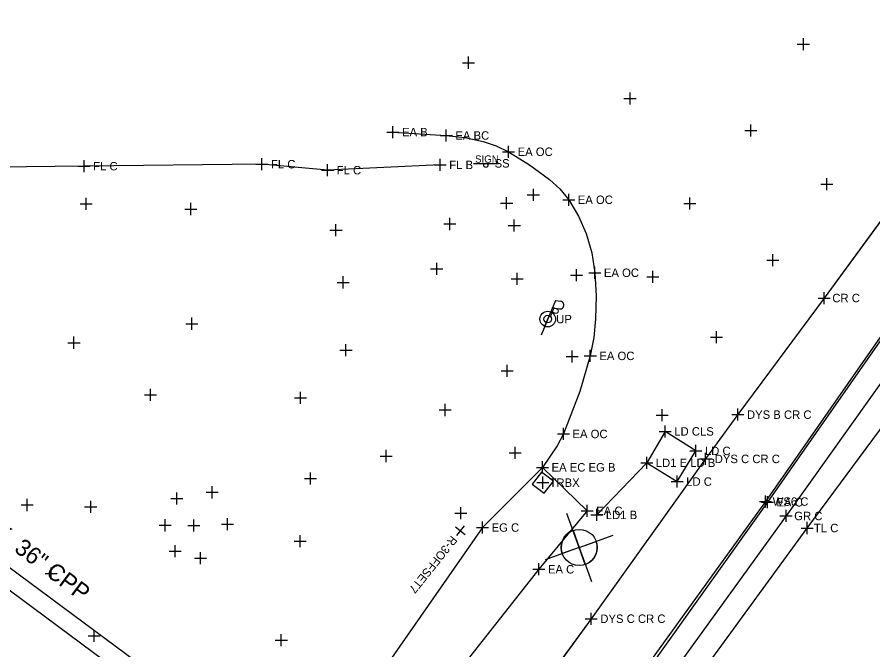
# Model space of a CAD drawing. Extents: x 1324236 to 1326110, y 459090 to 460782.
# Drawn here: x 1325315.8 to 1325457.8, y 460421.8 to 460526.7 of the extents above; entities that cross this region are included whole.
import ezdxf

# ---------------------------------------------------------------- set-up
doc = ezdxf.new("R2010")
doc.units = 0
for name, color, linetype in [('BD_X_Canopy', 7, 'Continuous'), ('DR_X_Ditch', 7, 'Continuous'), ('DT_X_Contour_Minor', 7, 'Continuous'), ('DT_X_Island', 7, 'Continuous'), ('DV_X_Property_Line', 7, 'Continuous'), ('GT_Project_Soil_Boring', 7, 'Continuous'), ('LT_X_Poles', 7, 'Continuous'), ('PM_X_CL_Double_Solid', 7, 'Continuous'), ('PM_X_Edge_Line', 7, 'Continuous'), ('PM_X_Parking_Lot_Stall', 7, 'Continuous'), ('PV_X_Shoulder', 7, 'Continuous'), ('RD_X_Concrete_Barrier', 7, 'Continuous'), ('RD_X_GR_Lt', 7, 'Continuous'), ('RW_X_CL', 7, 'Continuous'), ('RW_X_Esmt_SH', 7, 'Continuous'), ('RW_X_Fee_RW', 7, 'Continuous'), ('SC_Scratch1', 7, 'Continuous'), ('UT_X_Telecom', 7, 'Continuous'), ('VG_X_Flower_Bed', 7, 'Continuous')]:
    doc.layers.add(name, color=color, linetype=linetype)

msp = doc.modelspace()

# ---------------------------------------------------------------- linework, layer by layer
at = {"layer": 'BD_X_Canopy'}
msp.add_lwpolyline([(1325487.31, 460531.49), (1325482.01, 460524.62), (1325468.2, 460505.38), (1325449.72, 460480.14), (1325435.41, 460460.81), (1325430.06, 460453.47), (1325411.08, 460426.97), (1325392.29, 460401.31), (1325374.47, 460377.45), (1325359.08, 460355.34), (1325347.31, 460339.76), (1325334.63, 460323.86), (1325318.91, 460302.58), (1325303.42, 460281.57), (1325299.27, 460276.07), (1325289.28, 460262.48), (1325282.05, 460252.54), (1325264.96, 460229.27), (1325246.47, 460204.3), (1325228.59, 460180.03), (1325210.75, 460156.01)], dxfattribs=at)
at = {"layer": 'DR_X_Ditch'}
for points in [[(1325378.18, 460507.65), (1325387.03, 460507.09), (1325390.1, 460506.74), (1325393.12, 460506.1), (1325395.3, 460505.38), (1325397.36, 460504.39), (1325400.84, 460502.24), (1325404.13, 460499.82), (1325405.85, 460498.24), (1325407.34, 460496.43), (1325408.98, 460493.74), (1325410.25, 460490.84), (1325411.17, 460487.63), (1325411.67, 460484.33), (1325411.87, 460480.51), (1325411.8, 460476.68), (1325411.49, 460473.59), (1325410.92, 460470.55), (1325409.2, 460464.63), (1325406.46, 460457.61), (1325405.43, 460455.66), (1325402.99, 460452.07), (1325410.4, 460444.86), (1325402.39, 460435.17), (1325382.22, 460409.68)], [(1325459.02, 460473.66), (1325440.01, 460446.4), (1325420.89, 460420.01)]]:
    msp.add_lwpolyline(points, dxfattribs=at)
at = {"layer": 'DT_X_Contour_Minor'}
msp.add_line((1325391.53, 460502.47), (1325395.66, 460502.47), dxfattribs=at)
msp.add_circle((1325393.59, 460502.13), 0.344, dxfattribs=at)
at = {"layer": 'DT_X_Island'}
for p, q in [((1325468.2, 460505.38), (1325449.72, 460480.14)), ((1325449.72, 460480.14), (1325435.41, 460460.81)), ((1325435.41, 460460.81), (1325430.06, 460453.47)), ((1325430.06, 460453.47), (1325411.08, 460426.97)), ((1325411.08, 460426.97), (1325392.29, 460401.31))]:
    msp.add_line(p, q, dxfattribs=at)
at = {"layer": 'DV_X_Property_Line'}
for p, q in [((1325377.18, 460507.65), (1325379.18, 460507.65)), ((1325378.18, 460506.65), (1325378.18, 460508.65)), ((1325387.03, 460506.09), (1325387.03, 460508.09)), ((1325386.03, 460507.09), (1325388.03, 460507.09)), ((1325397.36, 460503.39), (1325397.36, 460505.39)), ((1325396.36, 460504.39), (1325398.36, 460504.39)), ((1325406.34, 460496.43), (1325408.34, 460496.43)), ((1325407.34, 460495.43), (1325407.34, 460497.43)), ((1325411.67, 460483.33), (1325411.67, 460485.33)), ((1325410.67, 460484.33), (1325412.67, 460484.33)), ((1325410.92, 460469.55), (1325410.92, 460471.55)), ((1325409.92, 460470.55), (1325411.92, 460470.55)), ((1325406.46, 460456.61), (1325406.46, 460458.61)), ((1325405.46, 460457.61), (1325407.46, 460457.61)), ((1325402.99, 460451.07), (1325402.99, 460453.07)), ((1325401.99, 460452.07), (1325403.99, 460452.07)), ((1325440.31, 460445.28), (1325440.31, 460447.28)), ((1325410.4, 460443.86), (1325410.4, 460445.86)), ((1325439.31, 460446.28), (1325441.31, 460446.28)), ((1325409.4, 460444.86), (1325411.4, 460444.86)), ((1325393.04, 460441.09), (1325393.04, 460443.09)), ((1325392.04, 460442.09), (1325394.04, 460442.09)), ((1325402.39, 460434.17), (1325402.39, 460436.17)), ((1325401.39, 460435.17), (1325403.39, 460435.17))]:
    msp.add_line(p, q, dxfattribs=at)
at = {"layer": 'GT_Project_Soil_Boring'}
for p, q in [((1325409.08, 460438.79), (1325407.05, 460444.43)), ((1325408.06, 460441.61), (1325409.08, 460438.79)), ((1325409.08, 460438.79), (1325414.72, 460440.81)), ((1325409.08, 460438.79), (1325411.9, 460439.8)), ((1325409.08, 460438.79), (1325403.43, 460436.76)), ((1325409.08, 460438.79), (1325406.25, 460437.77)), ((1325409.08, 460438.79), (1325411.1, 460433.14)), ((1325410.09, 460435.96), (1325409.08, 460438.79))]:
    msp.add_line(p, q, dxfattribs=at)
msp.add_circle((1325409.08, 460438.79), 3, dxfattribs=at)
for start, end in [(109.7344, 199.7344), (289.7344, 19.7344)]:
    msp.add_arc((1325409.08, 460438.79), 3, start, end, dxfattribs=at)
at = {"layer": 'LT_X_Poles'}
for points in [[(1325459.02, 460473.66), (1325440.01, 460446.4), (1325420.89, 460420.01)], [(1325435.41, 460460.81), (1325430.06, 460453.47), (1325411.08, 460426.97), (1325392.29, 460401.31), (1325374.47, 460377.45)]]:
    msp.add_lwpolyline(points, dxfattribs=at)
at = {"layer": 'PM_X_CL_Double_Solid'}
for p, q in [((1325326.93, 460502), (1325296.77, 460501.69)), ((1325356.44, 460502.33), (1325326.93, 460502)), ((1325367.34, 460501.34), (1325356.44, 460502.33)), ((1325386.01, 460502.22), (1325367.34, 460501.34)), ((1325435.41, 460460.81), (1325430.06, 460453.47)), ((1325430.06, 460453.47), (1325411.08, 460426.97)), ((1325411.08, 460426.97), (1325392.29, 460401.31))]:
    msp.add_line(p, q, dxfattribs=at)
at = {"layer": 'PM_X_Edge_Line'}
for p, q in [((1325459.02, 460473.66), (1325440.01, 460446.4)), ((1325440.01, 460446.4), (1325420.89, 460420.01))]:
    msp.add_line(p, q, dxfattribs=at)
at = {"layer": 'PM_X_Parking_Lot_Stall'}
for p, q in [((1325462.87, 460471.32), (1325443.39, 460444.01)), ((1325443.39, 460444.01), (1325424.35, 460417.69))]:
    msp.add_line(p, q, dxfattribs=at)
at = {"layer": 'PV_X_Shoulder'}
for points in [[(1325459.28, 460473.45), (1325440.31, 460446.28), (1325421.28, 460419.66)], [(1325402.99, 460452.07), (1325393.04, 460442.09), (1325373.73, 460414.41), (1325365.88, 460405.04), (1325350.78, 460385.39)]]:
    msp.add_lwpolyline(points, dxfattribs=at)
at = {"layer": 'RD_X_Concrete_Barrier'}
for p, q in [((1325405.13, 460479.72), (1325402.76, 460473.97)), ((1325405.13, 460479.72), (1325405.97, 460479.61)), ((1325404.62, 460478.5), (1325405.8, 460478.34))]:
    msp.add_line(p, q, dxfattribs=at)
msp.add_lwpolyline([(1325403.27, 460447.78), (1325404.79, 460449.76), (1325402.81, 460451.28), (1325401.29, 460449.3)], close=True, dxfattribs=at)
msp.add_circle((1325403.86, 460476.65), 1.3, dxfattribs=at)
msp.add_arc((1325405.9, 460478.97), 0.638, 261.5023, 83.7489, dxfattribs=at)
at = {"layer": 'RD_X_GR_Lt'}
for p, q in [((1325446.9, 460442.01), (1325466.37, 460468.29)), ((1325427.28, 460415.17), (1325446.9, 460442.01))]:
    msp.add_line(p, q, dxfattribs=at)
at = {"layer": 'RW_X_CL'}
for p, q in [((1325445.27, 460522.23), (1325447.27, 460522.23)), ((1325446.27, 460521.23), (1325446.27, 460523.23)), ((1325389.69, 460519.16), (1325391.69, 460519.16)), ((1325390.69, 460518.16), (1325390.69, 460520.16)), ((1325417.51, 460512.23), (1325417.51, 460514.23)), ((1325416.51, 460513.23), (1325418.51, 460513.23)), ((1325436.56, 460507.91), (1325438.56, 460507.91)), ((1325437.56, 460506.91), (1325437.56, 460508.91)), ((1325450.18, 460498.03), (1325450.18, 460500.03)), ((1325401.47, 460496.23), (1325401.47, 460498.23)), ((1325449.18, 460499.03), (1325451.18, 460499.03)), ((1325327.28, 460494.74), (1325327.28, 460496.74)), ((1325397.04, 460494.89), (1325397.04, 460496.89)), ((1325400.47, 460497.23), (1325402.47, 460497.23)), ((1325427.45, 460494.81), (1325427.45, 460496.81)), ((1325326.28, 460495.74), (1325328.28, 460495.74)), ((1325343.62, 460494.9), (1325345.62, 460494.9)), ((1325344.62, 460493.9), (1325344.62, 460495.9)), ((1325396.04, 460495.89), (1325398.04, 460495.89)), ((1325426.45, 460495.81), (1325428.45, 460495.81)), ((1325368.72, 460490.38), (1325368.72, 460492.38)), ((1325386.63, 460492.42), (1325388.63, 460492.42)), ((1325387.63, 460491.42), (1325387.63, 460493.42)), ((1325397.31, 460492.16), (1325399.31, 460492.16)), ((1325398.31, 460491.16), (1325398.31, 460493.16)), ((1325367.72, 460491.38), (1325369.72, 460491.38)), ((1325440.2, 460486.41), (1325442.2, 460486.41)), ((1325441.2, 460485.41), (1325441.2, 460487.41)), ((1325384.43, 460484.98), (1325386.43, 460484.98)), ((1325385.43, 460483.98), (1325385.43, 460485.98)), ((1325369.92, 460481.74), (1325369.92, 460483.74)), ((1325398.78, 460482.33), (1325398.78, 460484.33)), ((1325407.61, 460483.91), (1325409.61, 460483.91)), ((1325408.61, 460482.91), (1325408.61, 460484.91)), ((1325420.3, 460483.64), (1325422.3, 460483.64)), ((1325421.3, 460482.64), (1325421.3, 460484.64)), ((1325368.92, 460482.74), (1325370.92, 460482.74)), ((1325397.78, 460483.33), (1325399.78, 460483.33)), ((1325449.72, 460479.14), (1325449.72, 460481.14)), ((1325448.72, 460480.14), (1325450.72, 460480.14)), ((1325344.78, 460474.89), (1325344.78, 460476.89)), ((1325343.78, 460475.89), (1325345.78, 460475.89)), ((1325325.25, 460471.74), (1325325.25, 460473.74)), ((1325430.87, 460473.67), (1325432.87, 460473.67)), ((1325431.87, 460472.67), (1325431.87, 460474.67)), ((1325324.25, 460472.74), (1325326.25, 460472.74)), ((1325370.38, 460470.49), (1325370.38, 460472.49)), ((1325369.38, 460471.49), (1325371.38, 460471.49)), ((1325407.91, 460469.44), (1325407.91, 460471.44)), ((1325406.91, 460470.44), (1325408.91, 460470.44)), ((1325396.11, 460468.06), (1325398.11, 460468.06)), ((1325397.11, 460467.06), (1325397.11, 460469.06)), ((1325337.93, 460463.09), (1325337.93, 460465.09)), ((1325336.93, 460464.09), (1325338.93, 460464.09)), ((1325362.85, 460462.61), (1325362.85, 460464.61)), ((1325361.85, 460463.61), (1325363.85, 460463.61)), ((1325386.85, 460460.58), (1325386.85, 460462.58)), ((1325385.85, 460461.58), (1325387.85, 460461.58)), ((1325422.84, 460459.7), (1325422.84, 460461.7)), ((1325434.41, 460460.81), (1325436.41, 460460.81)), ((1325435.41, 460459.81), (1325435.41, 460461.81)), ((1325421.84, 460460.7), (1325423.84, 460460.7)), ((1325398.44, 460453.49), (1325398.44, 460455.49)), ((1325376.07, 460453.95), (1325378.07, 460453.95)), ((1325377.07, 460452.95), (1325377.07, 460454.95)), ((1325397.44, 460454.49), (1325399.44, 460454.49)), ((1325420.28, 460451.82), (1325420.28, 460453.82)), ((1325430.06, 460452.47), (1325430.06, 460454.47)), ((1325419.28, 460452.82), (1325421.28, 460452.82)), ((1325429.06, 460453.47), (1325431.06, 460453.47)), ((1325364.47, 460449.22), (1325364.47, 460451.22)), ((1325363.47, 460450.22), (1325365.47, 460450.22)), ((1325402.04, 460449.53), (1325404.04, 460449.53)), ((1325403.04, 460448.53), (1325403.04, 460450.53)), ((1325348.19, 460446.93), (1325348.19, 460448.93)), ((1325317.49, 460444.83), (1325317.49, 460446.83)), ((1325341.32, 460446.91), (1325343.32, 460446.91)), ((1325342.32, 460445.91), (1325342.32, 460447.91)), ((1325347.19, 460447.93), (1325349.19, 460447.93)), ((1325440.01, 460445.4), (1325440.01, 460447.4)), ((1325316.49, 460445.83), (1325318.49, 460445.83)), ((1325327.02, 460445.52), (1325329.02, 460445.52)), ((1325328.02, 460444.52), (1325328.02, 460446.52)), ((1325389.42, 460443.49), (1325389.42, 460445.49)), ((1325412, 460443.18), (1325412, 460445.18)), ((1325439.01, 460446.4), (1325441.01, 460446.4)), ((1325388.42, 460444.49), (1325390.42, 460444.49)), ((1325411, 460444.18), (1325413, 460444.18)), ((1325339.36, 460442.46), (1325341.36, 460442.46)), ((1325340.36, 460441.46), (1325340.36, 460443.46)), ((1325344.15, 460442.41), (1325346.15, 460442.41)), ((1325345.15, 460441.41), (1325345.15, 460443.41)), ((1325349.73, 460442.66), (1325351.73, 460442.66)), ((1325350.73, 460441.66), (1325350.73, 460443.66)), ((1325389.97, 460442.36), (1325388.73, 460440.79)), ((1325388.57, 460442.2), (1325390.13, 460440.95)), ((1325361.76, 460439.85), (1325363.76, 460439.85)), ((1325362.76, 460438.85), (1325362.76, 460440.85)), ((1325341.04, 460438.17), (1325343.04, 460438.17)), ((1325342.04, 460437.17), (1325342.04, 460439.17)), ((1325345.24, 460437.01), (1325347.24, 460437.01)), ((1325346.24, 460436.01), (1325346.24, 460438.01)), ((1325321.47, 460433.46), (1325321.47, 460435.46)), ((1325320.47, 460434.46), (1325322.47, 460434.46)), ((1325410.08, 460426.97), (1325412.08, 460426.97)), ((1325411.08, 460425.97), (1325411.08, 460427.97)), ((1325327.6, 460424.13), (1325329.6, 460424.13)), ((1325328.6, 460423.13), (1325328.6, 460425.13)), ((1325359.65, 460422.41), (1325359.65, 460424.41)), ((1325358.65, 460423.41), (1325360.65, 460423.41))]:
    msp.add_line(p, q, dxfattribs=at)
at = {"layer": 'RW_X_Esmt_SH'}
for p, q in [((1325325.93, 460502), (1325327.93, 460502)), ((1325326.93, 460501), (1325326.93, 460503)), ((1325355.44, 460502.33), (1325357.44, 460502.33)), ((1325356.44, 460501.33), (1325356.44, 460503.33)), ((1325367.34, 460500.34), (1325367.34, 460502.34)), ((1325385.01, 460502.22), (1325387.01, 460502.22)), ((1325386.01, 460501.22), (1325386.01, 460503.22)), ((1325366.34, 460501.34), (1325368.34, 460501.34)), ((1325422.35, 460458.03), (1325424.35, 460458.03)), ((1325423.35, 460457.03), (1325423.35, 460459.03)), ((1325428.44, 460453.8), (1325428.44, 460455.8)), ((1325427.44, 460454.8), (1325429.44, 460454.8)), ((1325424.33, 460449.71), (1325426.33, 460449.71)), ((1325425.33, 460448.71), (1325425.33, 460450.71)), ((1325442.39, 460444.01), (1325444.39, 460444.01)), ((1325443.39, 460443.01), (1325443.39, 460445.01)), ((1325446.9, 460441.01), (1325446.9, 460443.01)), ((1325445.9, 460442.01), (1325447.9, 460442.01))]:
    msp.add_line(p, q, dxfattribs=at)
at = {"layer": 'RW_X_Fee_RW'}
for p, q in [((1325423.35, 460458.03), (1325420.28, 460452.82)), ((1325428.44, 460454.8), (1325423.35, 460458.03)), ((1325425.33, 460449.71), (1325428.44, 460454.8)), ((1325412, 460444.18), (1325420.28, 460452.82)), ((1325420.28, 460452.82), (1325425.33, 460449.71))]:
    msp.add_line(p, q, dxfattribs=at)
at = {"layer": 'SC_Scratch1'}
msp.add_line((1325403.33, 460475.36), (1325404.13, 460477.31), dxfattribs=at)
msp.add_circle((1325403.86, 460476.65), 0.63, dxfattribs=at)
at = {"layer": 'VG_X_Flower_Bed'}
for p, q in [((1325304.91, 460442.59), (1325427.5, 460351.85)), ((1325303.12, 460440.18), (1325425.72, 460349.44))]:
    msp.add_line(p, q, dxfattribs=at)

# ---------------------------------------------------------------- texts
at = {"layer": 'DT_X_Contour_Minor'}
for s, height, p in [('SIGN', 1.205, (1325391.8, 460502.58)), ('SS', 1.4, (1325395.04, 460501.77))]:
    msp.add_text(s, height=height, dxfattribs=at).set_placement(p)
at = {"layer": 'DV_X_Property_Line'}
for s, p in [('EA B', (1325379.68, 460506.95)), ('EA BC', (1325388.53, 460506.39)), ('EA OC', (1325398.86, 460503.69)), ('EA OC', (1325408.84, 460495.73)), ('EA OC', (1325413.17, 460483.63)), ('EA OC', (1325412.42, 460469.85)), ('EA OC', (1325407.96, 460456.91)), ('EA EC EG B', (1325404.49, 460451.37)), ('EA C', (1325441.81, 460445.58)), ('EA C', (1325411.9, 460444.16)), ('EG C', (1325394.54, 460441.39)), ('EA C', (1325403.89, 460434.47))]:
    msp.add_text(s, height=1.4, dxfattribs=at).set_placement(p)
at = {"layer": 'RW_X_CL'}
for s, p in [('CR C', (1325451.08, 460479.44)), ('DYS B CR C', (1325436.91, 460460.11)), ('DYS C CR C', (1325431.56, 460452.77)), ('LD1 E LD B', (1325421.78, 460452.12)), ('TRBX', (1325404.16, 460448.83)), ('WS6 C', (1325441.18, 460445.7)), ('LD1 B', (1325413.5, 460443.48)), ('DYS C CR C', (1325412.58, 460426.27))]:
    msp.add_text(s, height=1.4, dxfattribs=at).set_placement(p)
msp.add_text('R-3OFFSET7', height=1.4, rotation=231.3852, dxfattribs=at).set_placement((1325387.87, 460440.84))
at = {"layer": 'RW_X_Esmt_SH'}
for s, p in [('FL C', (1325328.43, 460501.3)), ('FL C', (1325357.94, 460501.63)), ('FL C', (1325368.84, 460500.64)), ('FL B', (1325387.51, 460501.52)), ('LD CLS', (1325424.85, 460457.33)), ('LD C', (1325429.94, 460454.1)), ('LD C', (1325426.83, 460449.01)), ('GR C', (1325444.75, 460443.31)), ('TL C', (1325448.02, 460441.31))]:
    msp.add_text(s, height=1.4, dxfattribs=at).set_placement(p)
at = {"layer": 'SC_Scratch1'}
msp.add_text('P', height=1.5, rotation=337.5827, dxfattribs=at).set_placement((1325404.13, 460477.31))
msp.add_text('UP', height=1.4, dxfattribs=at).set_placement((1325405.26, 460475.95))
at = {"layer": 'UT_X_Telecom'}
msp.add_text('EX. 36" CPP', height=2.8, rotation=323.0615, dxfattribs=at).set_placement((1325309.52, 460442.49))

doc.saveas('drawing.dxf')
